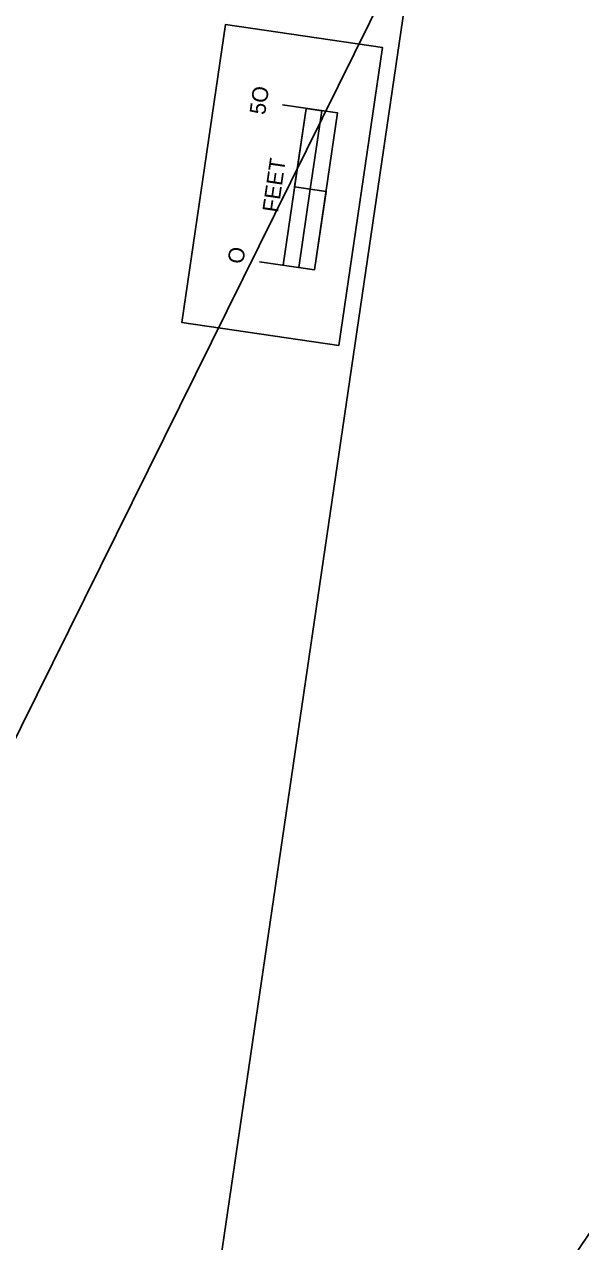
# Model space of a CAD drawing. Extents: x 14104283 to 14129344, y 8637090 to 8673339.
# Drawn here: x 14119276.6 to 14119452, y 8669521 to 8669905 of the extents above; entities that cross this region are included whole.
import ezdxf

# ---------------------------------------------------------------- set-up
doc = ezdxf.new("R2010")
doc.units = 0
for name, color, linetype in [('dsnNonPlotable', 7, 'Continuous'), ('dsnStdLabel', 7, 'Continuous'), ('dsnTextOverlapEven', 7, 'Continuous')]:
    doc.layers.add(name, color=color, linetype=linetype)

msp = doc.modelspace()

# ---------------------------------------------------------------- linework, layer by layer
at = {"layer": 'dsnNonPlotable'}
for points in [[(14118774.15, 8669147.84), (14119001.66, 8670698.74), (14119501.31, 8670625.45), (14119273.81, 8669074.54)], [(14118855.74, 8668834.3), (14119550.47, 8670239.43), (14120003.16, 8670015.61), (14119308.43, 8668610.48)]]:
    msp.add_lwpolyline(points, close=True, dxfattribs=at)
at = {"layer": 'dsnStdLabel'}
msp.add_arc((14120706.26, 8668675.12), 1512, 137.73115, 147.24256, dxfattribs=at)
at = {"layer": 'dsnTextOverlapEven'}
msp.add_line((14119371.73, 8669852.32), (14119361.83, 8669853.77), dxfattribs=at)
msp.add_line((14119371.73, 8669852.32), (14119361.83, 8669853.77), dxfattribs=at)
msp.add_line((14119371.73, 8669852.32), (14119361.83, 8669853.77), dxfattribs=at)
msp.add_line((14119371.73, 8669852.32), (14119361.83, 8669853.77), dxfattribs=at)
for points in [[(14119326.25, 8669810.98), (14119340.04, 8669904.97), (14119389.51, 8669897.72), (14119375.72, 8669803.72)], [(14119375.72, 8669803.72), (14119326.25, 8669810.98), (14119340.04, 8669904.97), (14119389.51, 8669897.72)], [(14119326.25, 8669810.98), (14119340.04, 8669904.97), (14119389.51, 8669897.72), (14119375.72, 8669803.72)], [(14119375.72, 8669803.72), (14119326.25, 8669810.98), (14119340.04, 8669904.97), (14119389.51, 8669897.72)], [(14119366.75, 8669853.05), (14119370.38, 8669877.78), (14119365.46, 8669878.5), (14119361.83, 8669853.77)], [(14119366.75, 8669853.05), (14119370.38, 8669877.78), (14119365.46, 8669878.5), (14119361.83, 8669853.77)], [(14119368.1, 8669827.58), (14119371.73, 8669852.32), (14119366.75, 8669853.05), (14119363.12, 8669828.31)], [(14119368.1, 8669827.58), (14119371.73, 8669852.32), (14119366.75, 8669853.05), (14119363.12, 8669828.31)]]:
    msp.add_lwpolyline(points, close=True, dxfattribs=at)
for points in [[(14119350.79, 8669830.12), (14119368.1, 8669827.58), (14119375.36, 8669877.05), (14119358.04, 8669879.59)], [(14119350.79, 8669830.12), (14119368.1, 8669827.58), (14119375.36, 8669877.05), (14119358.04, 8669879.59)], [(14119358.21, 8669829.03), (14119365.46, 8669878.5)], [(14119358.21, 8669829.03), (14119365.46, 8669878.5)]]:
    msp.add_lwpolyline(points, dxfattribs=at)

# ---------------------------------------------------------------- texts
for s, p in [('5O', (14119352.5, 8669876.29)), ('5O', (14119352.5, 8669876.29)), ('FEET', (14119356.57, 8669845.47)), ('FEET', (14119356.57, 8669845.47)), ('O', (14119345.6, 8669829.23)), ('O', (14119345.6, 8669829.23))]:
    msp.add_text(s, height=5, rotation=81.6547, dxfattribs=at).set_placement(p)

doc.saveas('drawing.dxf')
